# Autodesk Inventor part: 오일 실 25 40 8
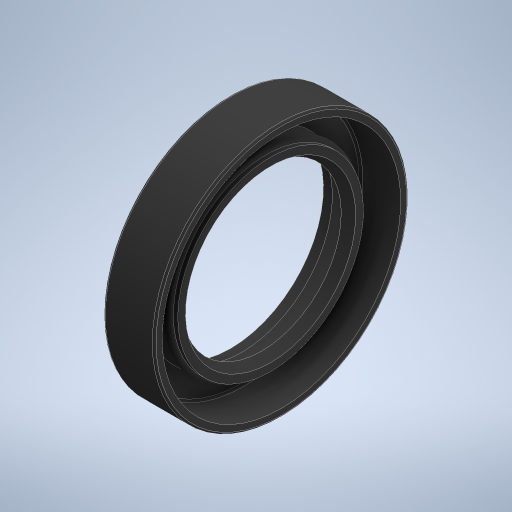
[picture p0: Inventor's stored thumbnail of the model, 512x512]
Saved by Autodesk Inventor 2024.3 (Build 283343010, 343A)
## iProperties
Created: 2025-11
Part Number: 오일 실 25 40 8
Material: 고무
Description: 오일-실
Document SubType Name: Modeling
Designer: PC2-15
Density: 0.93 g/cm^3
Appearance: 기본값
Author: jhkim
Sending System: Autodesk Inventor 2026
Preprocessor: ST-DEVELOPER v20.1
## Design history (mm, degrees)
node "오일 실 25 40 81"
node "솔리드1"
body "Solid1"
